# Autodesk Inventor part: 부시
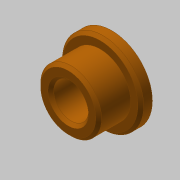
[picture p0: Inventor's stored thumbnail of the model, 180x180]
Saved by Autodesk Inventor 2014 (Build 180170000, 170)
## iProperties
Created: 2016-02
Part Number: 부시
Material: 강철, 연강
Document SubType Name: Modeling
Designer: test
Density: 1 g/cm^3
Appearance: 주황색
Author: test
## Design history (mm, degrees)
sketch "스케치1"
  geometry: C1 r 14 at (0, 0); C2 r 10.5 at (0, 0); 1 further point
  constraints: 2 centre point, 2 coincident
  dimensions: "d0" = 28 diameter of C1; "d1" = 21 diameter of C2
extrude "돌출1" new body sketch "스케치1" distance "d2" = 4; taper "d3" = 0 deg
extrude "돌출2" join sketch "스케치1" distance "d4" = 11; taper "d5" = 0 deg
hole "구멍1" diameter "d8" = 12; stored, may be unused: countersink angle "d12" = 90 deg, drill point angle "d14" = 118 deg; dims "d6" = 10, "d7" = 10, "d9" = 6, "d10" = 4, "d11" = 2, "d13" = 8
chamfer "모따기1" distance "d15" = 1; stored, may be unused: second distance "d16" = 2, angle "d17" = 45 deg
chamfer "모따기2" distance "d18" = 1; stored, may be unused: second distance "d19" = 2, angle "d20" = 45 deg
node "솔리드1"
